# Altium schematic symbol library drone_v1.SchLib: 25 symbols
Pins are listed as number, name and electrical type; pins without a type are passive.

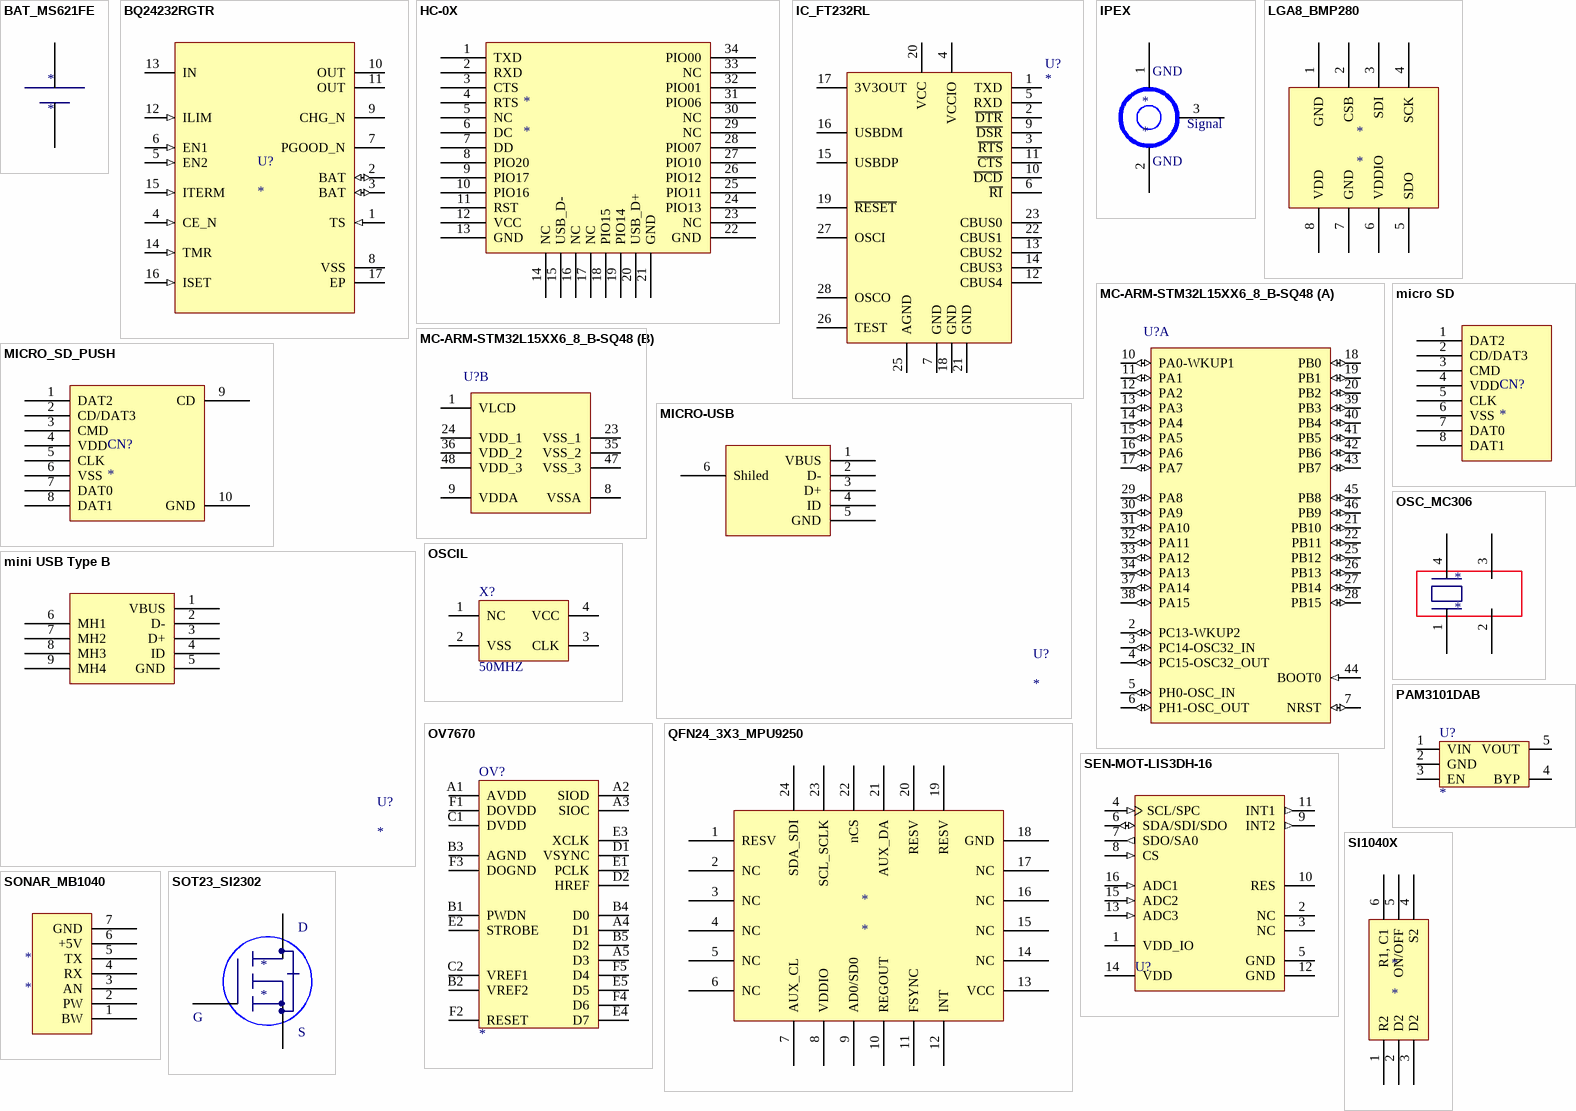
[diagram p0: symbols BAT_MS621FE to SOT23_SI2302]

## BAT_MS621FE
designator *
footprint BAT_MS621FE
pins: 1 +, 2 -

## BQ24232RGTR
designator U?
Imported; PartNumber: BQ24232RGTR; Alternate PartNumber: BQ24232RGTT; Manufacturer: Texas Instruments; CompType: IC; PIN_COUNT: 17
footprint RGT0016C
pins: 1 TS (in), 2 BAT (io), 3 BAT (io), 4 CE_N (in), 5 EN2 (in), 6 EN1 (in), 7 PGOOD_N (oc), 8 VSS (power), 9 CHG_N (oc), 10 OUT (power), 11 OUT (power), 12 ILIM (in), 13 IN (power), 14 TMR (in), 15 ITERM (in), 16 ISET (in), 17 EP (power)

## HC-0X
designator *
footprint HC-0X_4
pins: 1 TXD, 2 RXD, 3 CTS, 4 RTS, 5 NC, 6 DC, 7 DD, 8 PIO20, 9 PIO17, 10 PIO16, 11 RST, 12 VCC, 13 GND, 14 NC, 15 USB_D-, 16 NC, 17 NC, 18 PIO15, 19 PIO14, 20 USB_D+, 21 GND, 22 GND, 23 NC, 24 PIO13, 25 PIO11, 26 PIO12, 27 PIO10, 28 PIO07, 29 NC, 30 NC, 31 PIO06, 32 PIO01, 33 NC, 34 PIO00

## IC_FT232RL
designator U?
FT232R USB UART
footprint SSOP-28 (28-Pin SSOP 0.65 mm Pitch)
pins: 1 TXD, 2 ~{DTR}, 3 ~{RTS}, 4 VCCIO, 5 RXD, 6 ~{RI}, 7 GND, 8 NC hidden, 9 ~{DSR}, 10 ~{DCD}, 11 ~{CTS}, 12 CBUS4, 13 CBUS2, 14 CBUS3, 15 USBDP, 16 USBDM, 17 3V3OUT, 18 GND, 19 ~{RESET}, 20 VCC, 21 GND, 22 CBUS1, 23 CBUS0, 24 NC hidden, 25 AGND, 26 TEST, 27 OSCI, 28 OSCO
2 alternate drawings of the same symbol

## IPEX
designator *
footprint IPEX
pins: 1 GND, 2 GND, 3 Sig

## LGA8_BMP280
designator *
footprint LGA8_BMP280
pins: 1 GND, 2 CSB, 3 SDI, 4 SCK, 5 SDO, 6 VDDIO, 7 GND, 8 VDD

## MC-ARM-STM32L15XX6_8_B-SQ48
designator U?
footprint STM-LQFP48_N (QFP, 48-Leads, Body 7x7mm, Pitch 0.5mm, IPC Medium Density)
part A pins: 2 PC13-WKUP2 (io) "PC13-WKUP2/PC13/RTC_TAMP1/RTC_TS/RTC_OUT/WKUP2", 3 PC14-OSC32_IN (io) "PC14-OSC32_IN/PC14/OSC32_IN", 4 PC15-OSC32_OUT (io) "PC15-OSC32_OUT/PC15/OSC32_OUT", 5 PH0-OSC_IN (io) "PH0-OSC_IN/PH0/OSC_IN", 6 PH1-OSC_OUT (io) "PH1-OSC_OUT/PH1/OSC_OUT", 7 NRST (io), 10 PA0-WKUP1 (io) "PA0-WKUP1/PA0/WKUP1/USART2_CTS/ADC_IN0/TIM2_CH1_ETR/COMP1_INP", 11 PA1 (io) "PA1/USART2_RTS/ADC_IN1/TIM2_CH2/LCD_SEG0/COMP1_INP", 12 PA2 (io) "PA2/USART2_TX/ADC_IN2/TIM2_CH3/TIM9_CH1/LCD_SEG1/COMP1_INP", 13 PA3 (io) "PA3/USART2_RX/ADC_IN3/TIM2_CH4/TIM9_CH2/LCD_SEG2/COMP1_INP", 14 PA4 (io) "PA4/SPI1_NSS/USART2_CK/ADC_IN4/DAC_OUT1/COMP1_INP", 15 PA5 (io) "PA5/SPI1_SCK/ADC_IN5/DAC_OUT2/TIM2_CH1_ETR/COMP1_INP", 16 PA6 (io) "PA6/SPI1_MISO/ADC_IN6/TIM3_CH1/LCD_SEG3/TIM10_CH1/COMP1_INP", 17 PA7 (io) "PA7/SPI1_MOSI/ADC_IN7/TIM3_CH2/LCD_SEG4/TIM11_CH1/COMP1_INP", 18 PB0 (io) "PB0/ADC_IN8/TIM3_CH3/LCD_SEG5/COMP1_INP/VREF_OUT", 19 PB1 (io) "PB1/ADC_IN9/TIM3_CH4/LCD_SEG6/COMP1_INP/VREF_OUT", 20 PB2 (io) "PB2/BOOT1", 21 PB10 (io) "PB10/I2C2_SCL/USART3_TX/TIM2_CH3/LCD_SEG10", 22 PB11 (io) "PB11/I2C2_SDA/USART3_RX/TIM2_CH4/LCD_SEG11", 25 PB12 (io) "PB12/SPI2_NSS/I2C2_SMBA/USART3_CK/LCD_SEG12/ADC_IN18/COMP1_INP/TIM10_CH1", 26 PB13 (io) "PB13/SPI2_SCK/USART3_CTS/LCD_SEG13/ADC_IN19/COMP1_INP/TIM9_CH1", 27 PB14 (io) "PB14/SPI2_MISO/USART3_RTS/LCD_SEG14/ADC_IN20/COMP1_INP/TIM9_CH2", 28 PB15 (io) "PB15/SPI2_MOSI/LCD_SEG15/ADC_IN21/COMP1_INP/TIM11_CH1/RTC_REFIN", 29 PA8 (io) "PA8/USART1_CK/MCO/LCD_COM0", 30 PA9 (io) "PA9/USART1_TX/LCD_COM1", 31 PA10 (io) "PA10/USART1_RX/LCD_COM2", 32 PA11 (io) "PA11/USART1_CTS/USB_DM/SPI1_MISO", 33 PA12 (io) "PA12/USART1_RTS/USB_DP/SPI1_MOSI", 34 PA13 (io) "PA13/JTMS/SWDAT", 37 PA14 (io) "PA14/JTCK/SWCLK", 38 PA15 (io) "PA15/JTDI/TIM2_CH1_ETR/SPI1_NSS/LCD_SEG17", 39 PB3 (io) "PB3/JTDO/TIM2_CH2/SPI1_SCK/COMP2_INM/LCD_SEG7", 40 PB4 (io) "PB4/NJTRST/TIM3_CH1/SPI1_MISO/COMP2_INP/LCD_SEG8", 41 PB5 (io) "PB5/I2C1_SMBA/TIM3_CH2/SPI1_MOSI/COMP2_INP/LCD_SEG9", 42 PB6 (io) "PB6/I2C1_SCL/TIM4_CH1/USART1_TX", 43 PB7 (io) "PB7/I2C1_SDA/TIM4_CH2/USART1_RX/PVD_IN", 44 BOOT0 (in), 45 PB8 (io) "PB8/TIM4_CH3/I2C1_SCL/LCD_SEG16/TIM10_CH1", 46 PB9 (io) "PB9/TIM4_CH4/I2C1_SDA/LCD_COM3/TIM11_CH1"
part B pins: 1 VLCD (power), 8 VSSA (power), 9 VDDA (power), 23 VSS_1 (power), 24 VDD_1 (power), 35 VSS_2 (power), 36 VDD_2 (power), 47 VSS_3 (power), 48 VDD_3 (power)

## micro SD
designator CN?
footprint micro SD
pins: 1 DAT2, 2 CD/DAT3, 3 CMD, 4 VDD, 5 CLK, 6 VSS, 7 DAT0, 8 DAT1

## MICRO-USB
designator U?
footprint MICRO-USB
pins: 1 VBUS, 2 D-, 3 D+, 4 ID, 5 GND, 6 Shiled

## MICRO_SD_PUSH
designator CN?
footprint MICRO_SD_PUSH
pins: 1 DAT2, 2 CD/DAT3, 3 CMD, 4 VDD, 5 CLK, 6 VSS, 7 DAT0, 8 DAT1, 9 CD, 10 GND

## mini USB Type B
designator U?
footprint mini USB Type B
pins: 1 VBUS, 2 D-, 3 D+, 4 ID, 5 GND, 6 MH1, 7 MH2, 8 MH3, 9 MH4

## OSC_MC306
designator *
footprint OSC_MC306
pins: 1, 2, 3, 4

## OSCIL
designator X?, comment 50MHZ
footprint OSC_50M (for 50MHz)
pins: 1 NC, 2 VSS, 3 CLK, 4 VCC

## OV7670
designator OV?
footprint BGA24
footprint OV7670-18
footprint OV7670-22
pins: A1 AVDD, A2 SIOD, A3 SIOC, A4 D1, A5 D3, B1 PWDN, B2 VREF2, B3 AGND, B4 D0, B5 D2, C1 DVDD, C2 VREF1, D1 VSYNC, D2 HREF, E1 PCLK, E2 STROBE, E3 XCLK, E4 D7, E5 D5, F1 DOVDD, F2 RESET, F3 DOGND, F4 D6, F5 D4
2 alternate drawings of the same symbol

## PAM3101DAB
designator U?
footprint SOT-23-5
pins: 1 VIN, 2 GND, 3 EN, 4 BYP, 5 VOUT
2 alternate drawings of the same symbol

## QFN24_3X3_MPU9250
designator *
footprint QFN24_3X3_MPU9250
pins: 1 RESV, 2 NC, 3 NC, 4 NC, 5 NC, 6 NC, 7 AUX_CL, 8 VDDIO, 9 AD0/SD0, 10 REGOUT, 11 FSYNC, 12 INT, 13 VCC, 14 NC, 15 NC, 16 NC, 17 NC, 18 GND, 19 RESV, 20 RESV, 21 AUX_DA, 22 nCS, 23 SCL_SCLK, 24 SDA_SDI

## SEN-MOT-LIS3DH-16
designator U?
footprint LGA16-3X3X1_M (PQFN, 16-Leads, Body 3x3mm, Pitch 0.5mm, IPC Low Density)
pins: 1 VDD_IO (power), 2 NC, 3 NC, 4 SCL/SPC (in), 5 GND (power), 6 SDA/SDI/SDO (io), 7 SDO/SA0 (out), 8 CS (in), 9 INT2 (out), 10 RES, 11 INT1 (out), 12 GND (power), 13 ADC3 (in), 14 VDD (power), 15 ADC2 (in), 16 ADC1 (in)

## SI1040X
designator *
footprint SI1040X
pins: 1 R2, 2 D2, 3 D2, 4 S2, 5 ON/OFF, 6 R1, C1

## SONAR_MB1040
designator *
footprint SONAR_MB1040
pins: 1 BW, 2 PW, 3 AN, 4 RX, 5 TX, 6 +5V, 7 GND

## SOT23_SI2302
designator *
footprint SOT23_SI2302
pins: 1 G, 2 S, 3 D

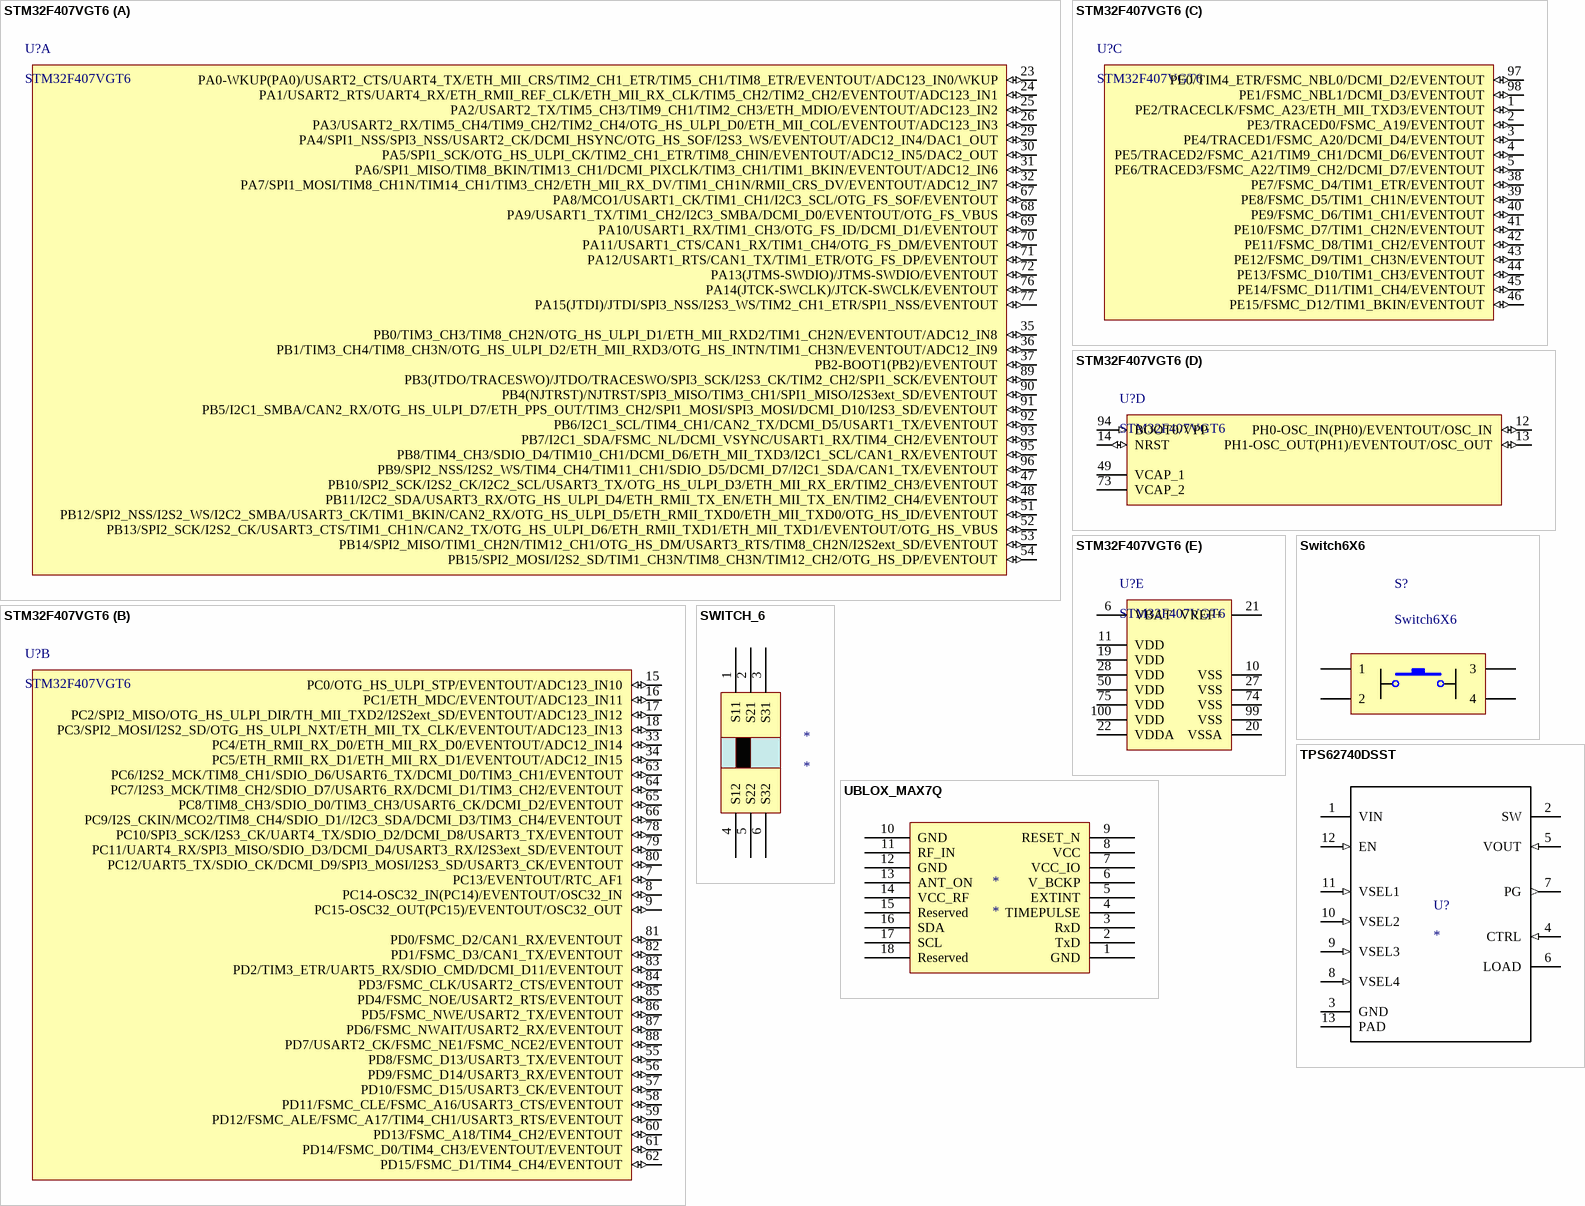
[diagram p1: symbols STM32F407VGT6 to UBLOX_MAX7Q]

## STM32F407VGT6
designator U?
footprint LQFP100_V (Thin QFP, 100-Leads, Body 14x14mm, Pitch 0.5mm, ST Recommended)
part A pins: 23 PA0-WKUP(PA0)/USART2_CTS/UART4_TX/ETH_MII_CRS/TIM2_CH1_ETR/TIM5_CH1/TIM8_ETR/EVENTOUT/ADC123_IN0/WKUP (io), 24 PA1/USART2_RTS/UART4_RX/ETH_RMII_REF_CLK/ETH_MII_RX_CLK/TIM5_CH2/TIM2_CH2/EVENTOUT/ADC123_IN1 (io), 25 PA2/USART2_TX/TIM5_CH3/TIM9_CH1/TIM2_CH3/ETH_MDIO/EVENTOUT/ADC123_IN2 (io), 26 PA3/USART2_RX/TIM5_CH4/TIM9_CH2/TIM2_CH4/OTG_HS_ULPI_D0/ETH_MII_COL/EVENTOUT/ADC123_IN3 (io), 29 PA4/SPI1_NSS/SPI3_NSS/USART2_CK/DCMI_HSYNC/OTG_HS_SOF/I2S3_WS/EVENTOUT/ADC12_IN4/DAC1_OUT (io), 30 PA5/SPI1_SCK/OTG_HS_ULPI_CK/TIM2_CH1_ETR/TIM8_CHIN/EVENTOUT/ADC12_IN5/DAC2_OUT (io), 31 PA6/SPI1_MISO/TIM8_BKIN/TIM13_CH1/DCMI_PIXCLK/TIM3_CH1/TIM1_BKIN/EVENTOUT/ADC12_IN6 (io), 32 PA7/SPI1_MOSI/TIM8_CH1N/TIM14_CH1/TIM3_CH2/ETH_MII_RX_DV/TIM1_CH1N/RMII_CRS_DV/EVENTOUT/ADC12_IN7 (io), 35 PB0/TIM3_CH3/TIM8_CH2N/OTG_HS_ULPI_D1/ETH_MII_RXD2/TIM1_CH2N/EVENTOUT/ADC12_IN8 (io), 36 PB1/TIM3_CH4/TIM8_CH3N/OTG_HS_ULPI_D2/ETH_MII_RXD3/OTG_HS_INTN/TIM1_CH3N/EVENTOUT/ADC12_IN9 (io), 37 PB2-BOOT1(PB2)/EVENTOUT (io), 47 PB10/SPI2_SCK/I2S2_CK/I2C2_SCL/USART3_TX/OTG_HS_ULPI_D3/ETH_MII_RX_ER/TIM2_CH3/EVENTOUT (io), 48 PB11/I2C2_SDA/USART3_RX/OTG_HS_ULPI_D4/ETH_RMII_TX_EN/ETH_MII_TX_EN/TIM2_CH4/EVENTOUT (io), 51 PB12/SPI2_NSS/I2S2_WS/I2C2_SMBA/USART3_CK/TIM1_BKIN/CAN2_RX/OTG_HS_ULPI_D5/ETH_RMII_TXD0/ETH_MII_TXD0/OTG_HS_ID/EVENTOUT (io), 52 PB13/SPI2_SCK/I2S2_CK/USART3_CTS/TIM1_CH1N/CAN2_TX/OTG_HS_ULPI_D6/ETH_RMII_TXD1/ETH_MII_TXD1/EVENTOUT/OTG_HS_VBUS (io), 53 PB14/SPI2_MISO/TIM1_CH2N/TIM12_CH1/OTG_HS_DM/USART3_RTS/TIM8_CH2N/I2S2ext_SD/EVENTOUT (io), 54 PB15/SPI2_MOSI/I2S2_SD/TIM1_CH3N/TIM8_CH3N/TIM12_CH2/OTG_HS_DP/EVENTOUT (io), 67 PA8/MCO1/USART1_CK/TIM1_CH1/I2C3_SCL/OTG_FS_SOF/EVENTOUT (io), 68 PA9/USART1_TX/TIM1_CH2/I2C3_SMBA/DCMI_D0/EVENTOUT/OTG_FS_VBUS (io), 69 PA10/USART1_RX/TIM1_CH3/OTG_FS_ID/DCMI_D1/EVENTOUT (io), 70 PA11/USART1_CTS/CAN1_RX/TIM1_CH4/OTG_FS_DM/EVENTOUT (io), 71 PA12/USART1_RTS/CAN1_TX/TIM1_ETR/OTG_FS_DP/EVENTOUT (io), 72 PA13(JTMS-SWDIO)/JTMS-SWDIO/EVENTOUT (io), 76 PA14(JTCK-SWCLK)/JTCK-SWCLK/EVENTOUT (io), 77 PA15(JTDI)/JTDI/SPI3_NSS/I2S3_WS/TIM2_CH1_ETR/SPI1_NSS/EVENTOUT (io), 89 PB3(JTDO/TRACESWO)/JTDO/TRACESWO/SPI3_SCK/I2S3_CK/TIM2_CH2/SPI1_SCK/EVENTOUT (io), 90 PB4(NJTRST)/NJTRST/SPI3_MISO/TIM3_CH1/SPI1_MISO/I2S3ext_SD/EVENTOUT (io), 91 PB5/I2C1_SMBA/CAN2_RX/OTG_HS_ULPI_D7/ETH_PPS_OUT/TIM3_CH2/SPI1_MOSI/SPI3_MOSI/DCMI_D10/I2S3_SD/EVENTOUT (io), 92 PB6/I2C1_SCL/TIM4_CH1/CAN2_TX/DCMI_D5/USART1_TX/EVENTOUT (io), 93 PB7/I2C1_SDA/FSMC_NL/DCMI_VSYNC/USART1_RX/TIM4_CH2/EVENTOUT (io), 95 PB8/TIM4_CH3/SDIO_D4/TIM10_CH1/DCMI_D6/ETH_MII_TXD3/I2C1_SCL/CAN1_RX/EVENTOUT (io), 96 PB9/SPI2_NSS/I2S2_WS/TIM4_CH4/TIM11_CH1/SDIO_D5/DCMI_D7/I2C1_SDA/CAN1_TX/EVENTOUT (io)
part B pins: 7 PC13/EVENTOUT/RTC_AF1 (io), 8 PC14-OSC32_IN(PC14)/EVENTOUT/OSC32_IN (io), 9 PC15-OSC32_OUT(PC15)/EVENTOUT/OSC32_OUT (io), 15 PC0/OTG_HS_ULPI_STP/EVENTOUT/ADC123_IN10 (io), 16 PC1/ETH_MDC/EVENTOUT/ADC123_IN11 (io), 17 PC2/SPI2_MISO/OTG_HS_ULPI_DIR/TH_MII_TXD2/I2S2ext_SD/EVENTOUT/ADC123_IN12 (io), 18 PC3/SPI2_MOSI/I2S2_SD/OTG_HS_ULPI_NXT/ETH_MII_TX_CLK/EVENTOUT/ADC123_IN13 (io), 33 PC4/ETH_RMII_RX_D0/ETH_MII_RX_D0/EVENTOUT/ADC12_IN14 (io), 34 PC5/ETH_RMII_RX_D1/ETH_MII_RX_D1/EVENTOUT/ADC12_IN15 (io), 55 PD8/FSMC_D13/USART3_TX/EVENTOUT (io), 56 PD9/FSMC_D14/USART3_RX/EVENTOUT (io), 57 PD10/FSMC_D15/USART3_CK/EVENTOUT (io), 58 PD11/FSMC_CLE/FSMC_A16/USART3_CTS/EVENTOUT (io), 59 PD12/FSMC_ALE/FSMC_A17/TIM4_CH1/USART3_RTS/EVENTOUT (io), 60 PD13/FSMC_A18/TIM4_CH2/EVENTOUT (io), 61 PD14/FSMC_D0/TIM4_CH3/EVENTOUT/EVENTOUT (io), 62 PD15/FSMC_D1/TIM4_CH4/EVENTOUT (io), 63 PC6/I2S2_MCK/TIM8_CH1/SDIO_D6/USART6_TX/DCMI_D0/TIM3_CH1/EVENTOUT (io), 64 PC7/I2S3_MCK/TIM8_CH2/SDIO_D7/USART6_RX/DCMI_D1/TIM3_CH2/EVENTOUT (io), 65 PC8/TIM8_CH3/SDIO_D0/TIM3_CH3/USART6_CK/DCMI_D2/EVENTOUT (io), 66 PC9/I2S_CKIN/MCO2/TIM8_CH4/SDIO_D1//I2C3_SDA/DCMI_D3/TIM3_CH4/EVENTOUT (io), 78 PC10/SPI3_SCK/I2S3_CK/UART4_TX/SDIO_D2/DCMI_D8/USART3_TX/EVENTOUT (io), 79 PC11/UART4_RX/SPI3_MISO/SDIO_D3/DCMI_D4/USART3_RX/I2S3ext_SD/EVENTOUT (io), 80 PC12/UART5_TX/SDIO_CK/DCMI_D9/SPI3_MOSI/I2S3_SD/USART3_CK/EVENTOUT (io), 81 PD0/FSMC_D2/CAN1_RX/EVENTOUT (io), 82 PD1/FSMC_D3/CAN1_TX/EVENTOUT (io), 83 PD2/TIM3_ETR/UART5_RX/SDIO_CMD/DCMI_D11/EVENTOUT (io), 84 PD3/FSMC_CLK/USART2_CTS/EVENTOUT (io), 85 PD4/FSMC_NOE/USART2_RTS/EVENTOUT (io), 86 PD5/FSMC_NWE/USART2_TX/EVENTOUT (io), 87 PD6/FSMC_NWAIT/USART2_RX/EVENTOUT (io), 88 PD7/USART2_CK/FSMC_NE1/FSMC_NCE2/EVENTOUT (io)
part C pins: 1 PE2/TRACECLK/FSMC_A23/ETH_MII_TXD3/EVENTOUT (io), 2 PE3/TRACED0/FSMC_A19/EVENTOUT (io), 3 PE4/TRACED1/FSMC_A20/DCMI_D4/EVENTOUT (io), 4 PE5/TRACED2/FSMC_A21/TIM9_CH1/DCMI_D6/EVENTOUT (io), 5 PE6/TRACED3/FSMC_A22/TIM9_CH2/DCMI_D7/EVENTOUT (io), 38 PE7/FSMC_D4/TIM1_ETR/EVENTOUT (io), 39 PE8/FSMC_D5/TIM1_CH1N/EVENTOUT (io), 40 PE9/FSMC_D6/TIM1_CH1/EVENTOUT (io), 41 PE10/FSMC_D7/TIM1_CH2N/EVENTOUT (io), 42 PE11/FSMC_D8/TIM1_CH2/EVENTOUT (io), 43 PE12/FSMC_D9/TIM1_CH3N/EVENTOUT (io), 44 PE13/FSMC_D10/TIM1_CH3/EVENTOUT (io), 45 PE14/FSMC_D11/TIM1_CH4/EVENTOUT (io), 46 PE15/FSMC_D12/TIM1_BKIN/EVENTOUT (io), 97 PE0/TIM4_ETR/FSMC_NBL0/DCMI_D2/EVENTOUT (io), 98 PE1/FSMC_NBL1/DCMI_D3/EVENTOUT (io)
part D pins: 12 PH0-OSC_IN(PH0)/EVENTOUT/OSC_IN (io), 13 PH1-OSC_OUT(PH1)/EVENTOUT/OSC_OUT (io), 14 NRST (io), 49 VCAP_1 (power), 73 VCAP_2 (power), 94 BOOT0/VPP (in)
part E pins: 6 VBAT (power), 10 VSS (power), 11 VDD (power), 19 VDD (power), 20 VSSA (power), 21 VREF+ (power), 22 VDDA (power), 27 VSS (power), 28 VDD (power), 50 VDD (power), 74 VSS (power), 75 VDD (power), 99 VSS (power), 100 VDD (power)

## Switch6X6
designator S?
Switch
footprint Switch6X6
pins: 1, 2, 3, 4

## SWITCH_6
designator *
footprint SWITCH_6
pins: 1 S11, 2 S21, 3 S31, 4 S12, 5 S22, 6 S32

## TPS62740DSST
designator U?
Imported; PartNumber: TPS62740DSS; Alternate Manufacturer: None; Manufacturer: Texas Instruments; CurrentTime: Not shown in title block; DocumentNumber: 1; SymbolCreator: a0411947; CompType: IC; U/M: EA; Designator: U?; PIN_COUNT: 13
footprint DSS0012A
pins: 1 VIN (power), 2 SW (power), 3 GND (power), 4 CTRL (in), 5 VOUT (in), 6 LOAD (power), 7 PG (out), 8 VSEL4 (in), 9 VSEL3 (in), 10 VSEL2 (in), 11 VSEL1 (in), 12 EN (in), 13 PAD (power)

## UBLOX_MAX7Q
designator *
footprint UBLOX_MAX7Q
pins: 1 GND, 2 TxD, 3 RxD, 4 TIMEPULSE, 5 EXTINT, 6 V_BCKP, 7 VCC_IO, 8 VCC, 9 RESET_N, 10 GND, 11 RF_IN, 12 GND, 13 ANT_ON, 14 VCC_RF, 15 Reserved, 16 SDA, 17 SCL, 18 Reserved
